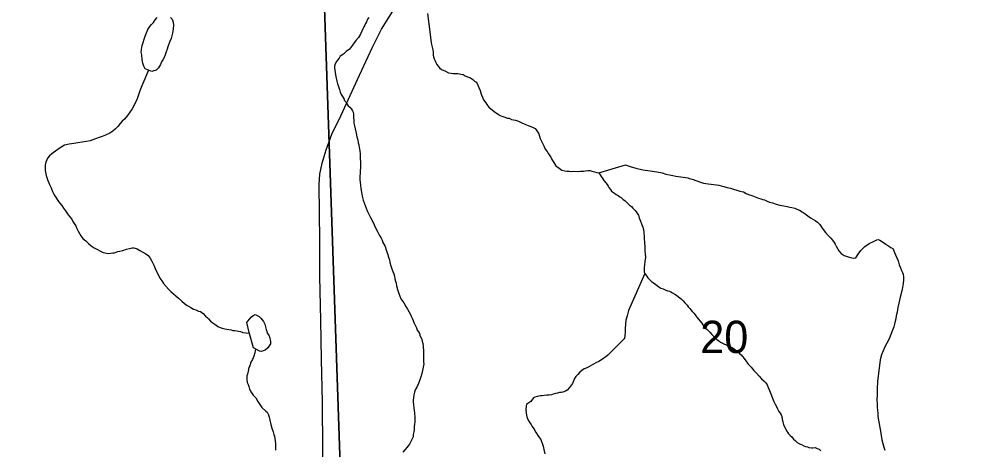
# Model space of a CAD drawing. Extents: x 2010165 to 2382125, y 1060529 to 1407316.
# Drawn here: x 2179406 to 2185920, y 1218222 to 1221171 of the extents above; entities that cross this region are included whole.
import ezdxf

# ---------------------------------------------------------------- set-up
doc = ezdxf.new("R2010")
doc.units = 0
for name, color, linetype in [('GM_X_Minor_Lake', 7, 'Continuous'), ('GM_X_Minor_River', 7, 'Continuous'), ('GM_X_Section', 7, 'Continuous'), ('GM_X_Section_Text', 7, 'Continuous'), ('GM_X_State_Route', 7, 'Continuous')]:
    doc.layers.add(name, color=color, linetype=linetype)

msp = doc.modelspace()

# ---------------------------------------------------------------- linework, layer by layer
at = {"layer": 'GM_X_Minor_Lake'}
for points in [[(2180270.6, 1221054.4), (2180278, 1221076.7), (2180287.4, 1221099), (2180300.9, 1221119.5), (2180312.6, 1221133.8), (2180326.2, 1221148.2), (2180337.7, 1221166.6), (2180351.4, 1221181)], [(2180443.6, 1221181.4), (2180454, 1221169.7), (2180460.5, 1221149.8), (2180463.1, 1221129.7), (2180461.8, 1221103.6), (2180456.6, 1221073.3), (2180447.5, 1221039), (2180436.2, 1221012.6), (2180430.6, 1220994.4), (2180425, 1220980.1), (2180421.4, 1220964), (2180413.8, 1220947.7), (2180406.4, 1220925.5), (2180398.9, 1220907.2), (2180391.2, 1220892.9), (2180381.6, 1220878.6), (2180374.1, 1220860.3), (2180360.7, 1220837.9), (2180345.1, 1220821.4), (2180323.2, 1220814.8), (2180315.2, 1220812.6)], [(2180315.2, 1220812.6), (2180270.6, 1220829.5), (2180260.1, 1220849.3), (2180253.5, 1220869.2), (2180248.8, 1220895.2), (2180246, 1220925.2), (2180243.5, 1220945.3), (2180245, 1220963.4), (2180248.3, 1220989.6), (2180270.6, 1221054.4)], [(2180965.2, 1219093.7), (2180972.9, 1219103.1), (2180984.6, 1219117.4), (2180996.3, 1219129.8), (2181010, 1219142.2), (2181023.9, 1219148.6), (2181036, 1219142.9), (2181050.3, 1219135.2), (2181062.6, 1219123.5), (2181071, 1219111.7), (2181081.3, 1219099.9), (2181089.8, 1219082.1), (2181094.3, 1219064.1), (2181098.8, 1219046.2), (2181103.2, 1219032.2), (2181105.5, 1219022.2), (2181115.9, 1219006.5), (2181124.4, 1218988.6), (2181126.7, 1218976.6), (2181129.1, 1218964.6), (2181127.5, 1218948.5), (2181119.9, 1218934.3), (2181110.2, 1218920), (2181092.6, 1218905.4), (2181078.7, 1218899.1), (2181066.7, 1218896.7), (2181052.7, 1218898.4), (2181011.9, 1218921.4), (2180983.3, 1219026.8)], [(2180983.3, 1219026.8), (2180965.2, 1219093.7)]]:
    msp.add_lwpolyline(points, dxfattribs=at)
at = {"layer": 'GM_X_Minor_River'}
for points in [[(2182205.1, 1221208.1), (2182228.9, 1221011.5), (2182231.3, 1220997.6), (2182235.9, 1220977.6), (2182240.4, 1220959.6), (2182242.8, 1220943.6), (2182243.1, 1220933.6), (2182243.3, 1220923.6), (2182245.7, 1220911.6), (2182250, 1220899.6), (2182256.4, 1220885.8), (2182260.7, 1220873.8), (2182267.1, 1220859.9), (2182277.5, 1220848.2), (2182285.8, 1220836.3), (2182300.2, 1220824.7), (2182326.5, 1220813.3), (2182346.8, 1220803.8), (2182365, 1220800.3), (2182377.1, 1220798.6), (2182397.1, 1220799.1), (2182411.2, 1220797.5), (2182423.3, 1220795.8), (2182433.3, 1220794), (2182447.5, 1220790.4), (2182461.7, 1220782.7), (2182478, 1220775.1), (2182498.2, 1220767.6), (2182514.5, 1220758), (2182526.9, 1220746.3), (2182539.1, 1220738.6), (2182564.7, 1220681), (2182571.4, 1220657.1), (2182579.9, 1220637.2), (2182586.3, 1220623.4), (2182594.7, 1220609.5), (2182603.1, 1220597.7), (2182611.4, 1220585.9), (2182623.9, 1220568.1), (2182648.5, 1220546.7), (2182669, 1220531.2), (2182687.4, 1220519.6), (2182701.7, 1220509.9), (2182713.8, 1220506.2), (2182734.1, 1220498.7), (2182752.3, 1220493.2), (2182764.3, 1220491.5), (2182780.6, 1220483.9), (2182806.8, 1220478.6), (2182827.1, 1220471.1), (2182849.4, 1220461.6), (2182871.7, 1220452.2), (2182894, 1220442.7), (2182912.2, 1220435.2), (2182928.5, 1220427.6), (2182940.7, 1220421.8), (2182949, 1220412), (2182957.3, 1220400.2), (2182965.7, 1220386.4), (2182976.6, 1220354.5), (2182987.3, 1220330.7), (2183000, 1220302.9), (2183010.6, 1220281.1), (2183023.2, 1220263.4), (2183033.6, 1220247.6), (2183042, 1220235.8), (2183048.2, 1220225.9), (2183052.6, 1220214), (2183060.9, 1220202.1), (2183069.3, 1220188.3), (2183083.9, 1220166.6), (2183106.4, 1220151.1), (2183124.8, 1220137.6), (2183145, 1220132.1), (2183159.1, 1220130.4), (2183175.2, 1220128.8), (2183191.3, 1220127.3), (2183201.2, 1220129.5), (2183235.4, 1220128.4), (2183251.4, 1220128.8), (2183273.4, 1220129.4), (2183285.4, 1220131.8), (2183301.4, 1220134.2), (2183317.4, 1220134.6), (2183329.5, 1220130.9), (2183347.7, 1220125.3), (2183363.9, 1220121.8), (2183378, 1220118.1), (2183386.4, 1220104.3), (2183392.7, 1220094.4), (2183405.2, 1220076.7), (2183411.5, 1220066.8), (2183426, 1220049.1), (2183434.3, 1220039.3), (2183440.6, 1220027.4), (2183446.9, 1220017.5), (2183457.3, 1220003.7), (2183463.6, 1219993.9)], [(2181801.2, 1221181), (2181793.5, 1221170.8), (2181786, 1221152.5), (2181780.3, 1221140.3), (2181774.5, 1221130.1), (2181768.9, 1221117.9), (2181761.2, 1221103.6), (2181753.6, 1221087.4), (2181744.2, 1221067.1), (2181730.7, 1221044.6), (2181713.2, 1221024.1), (2181690, 1220991.3), (2181668.7, 1220964.7), (2181647.1, 1220948), (2181629.5, 1220931.5), (2181617.7, 1220923.2), (2181605.8, 1220916.8), (2181598.2, 1220902.6), (2181588.5, 1220890.3), (2181580.8, 1220880), (2181571.2, 1220863.7), (2181567.5, 1220849.6), (2181565.9, 1220837.5), (2181573.2, 1220789.5), (2181577.8, 1220767.5), (2181582.4, 1220745.6), (2181586.9, 1220727.6), (2181593.4, 1220709.7), (2181600, 1220687.8), (2181606.5, 1220669.9), (2181612.9, 1220654), (2181621.3, 1220640.1), (2181629.7, 1220626.3), (2181634, 1220616.4), (2181644.3, 1220604.6), (2181648.6, 1220594.7), (2181661.1, 1220576.9), (2181671.4, 1220567.2), (2181683.8, 1220553.4), (2181690.1, 1220543.6), (2181694.4, 1220533.6), (2181696.8, 1220519.6), (2181697.3, 1220497.6), (2181699.9, 1220475.6), (2181700.4, 1220457.5), (2181704.9, 1220439.6), (2181709.5, 1220419.6), (2181714.3, 1220389.6), (2181721, 1220365.7), (2181725.6, 1220341.7), (2181730.1, 1220323.8), (2181734.5, 1220309.8), (2181737, 1220291.8), (2181739.6, 1220269.8), (2181742.2, 1220245.8), (2181742.9, 1220219.7), (2181745.8, 1220189.6), (2181744.6, 1220159.5), (2181743.5, 1220125.3), (2181741.9, 1220111.2), (2181740.2, 1220097.1), (2181740.6, 1220085.1), (2181740.9, 1220071), (2181743.4, 1220055), (2181743.9, 1220035), (2181746.6, 1220010.9), (2181751.2, 1219987), (2181756, 1219959), (2181762.8, 1219931.1), (2181790.8, 1219859.5), (2181801.4, 1219835.7), (2181814.1, 1219811.9), (2181826.8, 1219788.2), (2181839.5, 1219762.4), (2181850.2, 1219736.6), (2181862.9, 1219712.8), (2181875.6, 1219689.1), (2181886.1, 1219671.3), (2181894.5, 1219657.4), (2181898.9, 1219641.5), (2181905.2, 1219629.6), (2181911.6, 1219617.7), (2181915.9, 1219607.8), (2181918.2, 1219595.8), (2181922.5, 1219583.9), (2181926.9, 1219571.9), (2181931.2, 1219560), (2181935.5, 1219548.1), (2181939.9, 1219534.1), (2181944.2, 1219522.2), (2181946.7, 1219504.2), (2181953.3, 1219482.3), (2181959.9, 1219462.4), (2181966.4, 1219442.5), (2181972.9, 1219426.6), (2181977.3, 1219410.6)], [(2180292.5, 1220821.2), (2180247.7, 1220714.5), (2180232.6, 1220679.9), (2180212.1, 1220619.2), (2180181.8, 1220556.1), (2180148.9, 1220511.1), (2180127.5, 1220486.4), (2180111.8, 1220471.9), (2180098.2, 1220455.5), (2180082.7, 1220435), (2180067.2, 1220418.6), (2180047.5, 1220404), (2180027.8, 1220389.4), (2179998.1, 1220376.6), (2179976.3, 1220368), (2179954.4, 1220359.4), (2179930.6, 1220350.7), (2179910.7, 1220344.2), (2179892.9, 1220337.7), (2179868.9, 1220333), (2179839, 1220328.2), (2179809, 1220323.4), (2179781.1, 1220318.7), (2179749.1, 1220315.8), (2179717.2, 1220307), (2179681.7, 1220285.9), (2179656.1, 1220267.2), (2179640.4, 1220254.7), (2179630.6, 1220248.5), (2179614.9, 1220234), (2179601.3, 1220219.6), (2179595.6, 1220207.4), (2179590, 1220191.2), (2179584.5, 1220170.9), (2179585.5, 1220134.8), (2179592.4, 1220100.9), (2179603.4, 1220067), (2179614.2, 1220039.2), (2179626.8, 1220015.4), (2179635.5, 1219991.6), (2179641.9, 1219977.7), (2179650.3, 1219961.8), (2179675.5, 1219922.3), (2179685.8, 1219910.6), (2179698.3, 1219894.8), (2179710.8, 1219877.1), (2179723.3, 1219857.3), (2179737.9, 1219837.6), (2179752.4, 1219819.9), (2179766.9, 1219802.3), (2179775.4, 1219786.4), (2179783.8, 1219770.6), (2179794.3, 1219754.8), (2179802.8, 1219736.9), (2179811.3, 1219719.1), (2179819.7, 1219703.3), (2179830.2, 1219687.5), (2179842.7, 1219669.7), (2179863.2, 1219652.2), (2179881.7, 1219634.6), (2179900.2, 1219619), (2179920.6, 1219605.5), (2179943, 1219594.1), (2179963.4, 1219582.5), (2179981.7, 1219573), (2180003.8, 1219569.6), (2180020, 1219565.9), (2180033.9, 1219568.3), (2180047.9, 1219570.7), (2180059.9, 1219571), (2180071.8, 1219575.3), (2180081.8, 1219579.6), (2180095.7, 1219582), (2180115.7, 1219586.6), (2180141.5, 1219595.3), (2180163.4, 1219599.8), (2180181.4, 1219604.3), (2180191.4, 1219604.6), (2180201.5, 1219602.8), (2180215.6, 1219597.2), (2180233.9, 1219587.6), (2180254.3, 1219576.1), (2180274.7, 1219564.6), (2180291, 1219553), (2180303.5, 1219535.3), (2180316.2, 1219513.5), (2180328.9, 1219485.7), (2180341.9, 1219451.9), (2180358.7, 1219422.3), (2180371.4, 1219398.5), (2180384, 1219378.8), (2180394.5, 1219361), (2180429.6, 1219321.7), (2180446.1, 1219306.1), (2180464.5, 1219290.5), (2180481, 1219276.9), (2180497.4, 1219261.3), (2180520.1, 1219239.8), (2180538.5, 1219224.2), (2180556.9, 1219210.6), (2180575.2, 1219201.1)], [(2183378, 1220118.1), (2183561, 1220173.1), (2183591.4, 1220161.9), (2183631.8, 1220150.9), (2183680.2, 1220140.1), (2183728.6, 1220131.4), (2183774.9, 1220124.5), (2183811.2, 1220117.5), (2183837.4, 1220110.1), (2183861.7, 1220104.7), (2183883.8, 1220101.3), (2183906, 1220095.9), (2183922.1, 1220092.3), (2183940.2, 1220090.7), (2183956.3, 1220089.1), (2183972.5, 1220085.6), (2183986.5, 1220083.9), (2183996.7, 1220080.2), (2184008.8, 1220076.5), (2184024.9, 1220072.9), (2184043.2, 1220065.3), (2184067.4, 1220057.9), (2184093.8, 1220048.6), (2184126, 1220043.4), (2184148.1, 1220042), (2184164.2, 1220038.4), (2184184.3, 1220036.9), (2184200.5, 1220033.3), (2184216.6, 1220029.7), (2184234.8, 1220024.2), (2184257, 1220018.8), (2184279.2, 1220013.3), (2184343.9, 1219992.9), (2184354, 1219991.2), (2184368.1, 1219987.6), (2184386.4, 1219978), (2184402.7, 1219970.4), (2184425, 1219962.9), (2184449.3, 1219953.5), (2184471.5, 1219946.1), (2184487.7, 1219940.5), (2184499.8, 1219936.8), (2184512, 1219933.1), (2184530.2, 1219925.6), (2184546.5, 1219917.9), (2184566.7, 1219912.5), (2184592.9, 1219905.1), (2184617.2, 1219897.7), (2184645.4, 1219892.4), (2184667.6, 1219887), (2184685.8, 1219883.5), (2184699.9, 1219881.8), (2184720.1, 1219876.3), (2184734.2, 1219870.7), (2184752.5, 1219863.1), (2184770.9, 1219851.6), (2184791.3, 1219838.1), (2184809.7, 1219824.5), (2184828.1, 1219810.9), (2184844.4, 1219801.3), (2184858.7, 1219791.6), (2184875.1, 1219780), (2184891.5, 1219764.4), (2184908.3, 1219738.7), (2184931.1, 1219711.2), (2184949.7, 1219689.6), (2184966.2, 1219672), (2184978.6, 1219658.2), (2184991.1, 1219642.5), (2184997.4, 1219630.6), (2185003.8, 1219616.8), (2185012.2, 1219600.9), (2185022.7, 1219585.1), (2185037.2, 1219567.4), (2185057.7, 1219551.9), (2185092.1, 1219540.8), (2185120.3, 1219535.5), (2185138.3, 1219535.9), (2185153.6, 1219562.5), (2185173, 1219587.1), (2185200.4, 1219613.9), (2185229.9, 1219634.8), (2185259.6, 1219649.6), (2185281.4, 1219660.2), (2185291.3, 1219662.5), (2185303.5, 1219656.8), (2185321.8, 1219647.2), (2185344.3, 1219629.7), (2185364.8, 1219616.2), (2185379.1, 1219606.6), (2185393.3, 1219598.9), (2185397.7, 1219584.9), (2185404, 1219573.1), (2185410.5, 1219557.2), (2185419, 1219537.3), (2185427.6, 1219515.5), (2185436.3, 1219489.6), (2185445, 1219467.7), (2185451.5, 1219449.8)], [(2183463.6, 1219993.9), (2183484.1, 1219978.3), (2183496.3, 1219970.6), (2183510.5, 1219963), (2183520.8, 1219955.2), (2183530.9, 1219949.4), (2183543.3, 1219937.7), (2183557.6, 1219926.1), (2183576.2, 1219908.5), (2183588.5, 1219896.8), (2183600.8, 1219887.1), (2183611.1, 1219877.3), (2183627.6, 1219861.6), (2183633.9, 1219851.8), (2183648.5, 1219828.1), (2183655, 1219810.2), (2183678.8, 1219746.5), (2183683.2, 1219730.6), (2183685.8, 1219710.6), (2183686, 1219700.5), (2183688.4, 1219686.6), (2183688.9, 1219670.5), (2183689.7, 1219640.4), (2183692.4, 1219614.4), (2183693.2, 1219584.3), (2183695.8, 1219562.2), (2183696.4, 1219540.2), (2183693.1, 1219512), (2183689.8, 1219487.8), (2183688.3, 1219469.7), (2183688.5, 1219459.6), (2183688.8, 1219449.6), (2183689.1, 1219439.6), (2183693.4, 1219429.7), (2183703.8, 1219413.9), (2183714.2, 1219400.1), (2183726.6, 1219386.4), (2183739, 1219374.6), (2183751.3, 1219364.9), (2183767.6, 1219353.3), (2183788.1, 1219337.8), (2183802.3, 1219330.1), (2183818.5, 1219324.5), (2183832.8, 1219316.9), (2183848.9, 1219311.3), (2183861.1, 1219307.6), (2183871.2, 1219303.8), (2183881.4, 1219298.1), (2183897.7, 1219288.5), (2183909.9, 1219280.8), (2183924.3, 1219269.1), (2183940.7, 1219255.5), (2183955.1, 1219241.8), (2183967.5, 1219228.1), (2183982, 1219212.4), (2183990.3, 1219200.5), (2184000.6, 1219190.8), (2184006.9, 1219180.9), (2184017.2, 1219169.1), (2184027.6, 1219157.3), (2184037.9, 1219145.6), (2184046.2, 1219133.8), (2184083.6, 1219088.6), (2184098.3, 1219062.8), (2184120.8, 1219045.3), (2184137.3, 1219027.7), (2184151.8, 1219012), (2184168.3, 1218996.4), (2184184.7, 1218980.8), (2184199.1, 1218969.1), (2184211.4, 1218959.4), (2184225.6, 1218951.7), (2184237.8, 1218946), (2184252, 1218940.4), (2184264.2, 1218934.7), (2184280.4, 1218927.1), (2184290.6, 1218923.3), (2184309, 1218909.8), (2184321.2, 1218902), (2184331.5, 1218892.3), (2184341.8, 1218882.5), (2184352.1, 1218872.7), (2184362.4, 1218861), (2184372.8, 1218847.2), (2184385.3, 1218831.4), (2184399.9, 1218809.7), (2184420.5, 1218788.2), (2184439.2, 1218766.6), (2184457.7, 1218747), (2184476.3, 1218727.4), (2184492.9, 1218707.8), (2184509.3, 1218692.1), (2184521.7, 1218680.4), (2184532.1, 1218666.6), (2184538.6, 1218648.8), (2184547.1, 1218628.9), (2184555.8, 1218605), (2184568.6, 1218575.2), (2184577.3, 1218553.4), (2184585.8, 1218535.5), (2184594.2, 1218519.7)], [(2185451.5, 1219449.8), (2185457.9, 1219435.9), (2185462.2, 1219424), (2185464.7, 1219406), (2185465.2, 1219385.9), (2185461.8, 1219361.8), (2185455, 1219319.4), (2185442.4, 1219266.9), (2185433.4, 1219226.5), (2185426.2, 1219196.2), (2185421, 1219165.9), (2185415.7, 1219139.7), (2185412.2, 1219119.5), (2185408.7, 1219103.3), (2185403.2, 1219083.1), (2185397.7, 1219064.9), (2185390.2, 1219042.6), (2185379, 1219012.2), (2185365.8, 1218981.7), (2185350.5, 1218953.2), (2185337.2, 1218926.8), (2185325.9, 1218900.4), (2185314.6, 1218872), (2185305.5, 1218839.6), (2185287.4, 1218690.5), (2185284.8, 1218640.3), (2185283.9, 1218598.1), (2185282.8, 1218565.9), (2185283.5, 1218537.8), (2185284.2, 1218513.8), (2185286.8, 1218491.8), (2185289.3, 1218473.7), (2185289.9, 1218451.7), (2185292.6, 1218425.6), (2185297.2, 1218401.7), (2185302, 1218375.7), (2185306.7, 1218349.7), (2185311.5, 1218319.7), (2185316.2, 1218291.7), (2185323, 1218265.8), (2185329.7, 1218239.9), (2185336.2, 1218220)], [(2181977.3, 1219410.6), (2181979.8, 1219392.6), (2181984.3, 1219376.7), (2181988.6, 1219362.7), (2181991.1, 1219344.7), (2181997.8, 1219320.8), (2182008.6, 1219293), (2182021.6, 1219255.2), (2182042.4, 1219227.6), (2182055.1, 1219203.8), (2182067.6, 1219186.1), (2182076.1, 1219170.3), (2182084.6, 1219152.4), (2182093, 1219136.6), (2182099.4, 1219122.7), (2182105.8, 1219108.8), (2182110.2, 1219094.9), (2182116.6, 1219081), (2182123, 1219067.1), (2182129.2, 1219057.2), (2182133.7, 1219041.3), (2182142, 1219029.4), (2182148.3, 1219019.6), (2182152.6, 1219007.6), (2182165.5, 1218977.8), (2182167.8, 1218965.9), (2182172.2, 1218949.9), (2182174.7, 1218933.9), (2182175.7, 1218895.8), (2182176.5, 1218865.7), (2182177.2, 1218841.6), (2182177.7, 1218821.6), (2182178, 1218811.5), (2182174.6, 1218787.3), (2182169.2, 1218765.1), (2182161.9, 1218736.8), (2182152.7, 1218708.4), (2182141.5, 1218676), (2182130.1, 1218651.6), (2182120.6, 1218633.3), (2182115, 1218617.1), (2182111.5, 1218598.9), (2182108, 1218578.8), (2182106.5, 1218562.7), (2182104.8, 1218550.6), (2182107.3, 1218530.6), (2182109.9, 1218508.5), (2182112.4, 1218492.5), (2182114.8, 1218478.6), (2182115.1, 1218466.5), (2182117.5, 1218452.5), (2182117.7, 1218442.5), (2182118.1, 1218428.4), (2182116.5, 1218412.3), (2182114.9, 1218398.2), (2182113.3, 1218382.1), (2182111.9, 1218362), (2182110.3, 1218345.9), (2182106.8, 1218327.7), (2182105.2, 1218311.6), (2182101.5, 1218301.5), (2182080.5, 1218260.8), (2182063.1, 1218238.2), (2182035.8, 1218207.4)], [(2183693.1, 1219430.2), (2183579.9, 1219175.7), (2183570.8, 1219139.3), (2183563.6, 1219109), (2183560.4, 1219080.8), (2183559.1, 1219054.7), (2183557.8, 1219028.5), (2183556.4, 1219004.4), (2183553, 1218984.2), (2183533.5, 1218963.6), (2183510, 1218940.9), (2183482.7, 1218914.1), (2183457.3, 1218889.3), (2183439.7, 1218870.8), (2183426, 1218858.4), (2183412.2, 1218850), (2183396.5, 1218837.6), (2183376.7, 1218827), (2183356.9, 1218818.4), (2183309.5, 1218791.1), (2183291.7, 1218782.6), (2183277.8, 1218776.2), (2183262.1, 1218765.8), (2183248.4, 1218753.3), (2183234.7, 1218738.9), (2183221.1, 1218724.5), (2183211.4, 1218710.2), (2183198.3, 1218677.7), (2183177, 1218649.1), (2183161.4, 1218630.6), (2183149.6, 1218624.2), (2183131.7, 1218617.8), (2183119.7, 1218615.4), (2183107.7, 1218615.1), (2183093.8, 1218610.7), (2183079.8, 1218608.3), (2183065.9, 1218604), (2183054, 1218599.6), (2183038, 1218597.2), (2183022, 1218596.8), (2183004, 1218594.3), (2182990, 1218591.9), (2182978, 1218591.6), (2182966, 1218589.3), (2182956.1, 1218587), (2182940.1, 1218582.6), (2182930.2, 1218578.3), (2182910.8, 1218553.7), (2182891.2, 1218539.1), (2182881.3, 1218532.8), (2182879.6, 1218522.8), (2182878.2, 1218498.6), (2182878.9, 1218474.6), (2182883.6, 1218448.6), (2182894.3, 1218424.8), (2182904.8, 1218407), (2182913.1, 1218395.1), (2182921.5, 1218383.3), (2182931.9, 1218367.5), (2182940.3, 1218355.7), (2182948.7, 1218339.8), (2182959.3, 1218320.1), (2182971.7, 1218304.3), (2182980.1, 1218292.5), (2182995.3, 1218246.7), (2183001.9, 1218224.8), (2183006.7, 1218194.8)], [(2180575.2, 1219201.1), (2180589.5, 1219191.4), (2180601.7, 1219185.7), (2180615.9, 1219180), (2180634.2, 1219172.5), (2180648.3, 1219168.8), (2180666.7, 1219155.3), (2180683.2, 1219137.6), (2180693.5, 1219127.9), (2180703.8, 1219118.1), (2180716.3, 1219102.4), (2180734.7, 1219088.8), (2180753, 1219077.2), (2180767.3, 1219067.6), (2180783.6, 1219060), (2180797.8, 1219054.3), (2180815.9, 1219050.8), (2180830, 1219049.1), (2180844.1, 1219045.5), (2180858.2, 1219043.9), (2180870.4, 1219040.2), (2180882.4, 1219038.5), (2180898.5, 1219036.9), (2180908.6, 1219035.1), (2180922.7, 1219031.5), (2180938.9, 1219025.9), (2180985, 1219020.7)], [(2181025.4, 1218913.8), (2181020.9, 1218885.5), (2181013.5, 1218863.2), (2181004.1, 1218840.9), (2180994.5, 1218822.6), (2180987.2, 1218798.3), (2180979.5, 1218786), (2180976.1, 1218761.8), (2180970.6, 1218741.6), (2180967, 1218729.5), (2180965.3, 1218717.4), (2180965.7, 1218703.3), (2180968.2, 1218683.3), (2180974.6, 1218669.4), (2180979, 1218655.5), (2180983.5, 1218637.5), (2180996.1, 1218617.8), (2181010.7, 1218596.1), (2181027.2, 1218578.4), (2181041.9, 1218552.7), (2181069.1, 1218511.3), (2181095.8, 1218487.9), (2181106, 1218480.1), (2181114.5, 1218462.3), (2181119, 1218446.3), (2181123.5, 1218426.4), (2181130.4, 1218396.4), (2181137.1, 1218370.5), (2181145.7, 1218346.6), (2181152.2, 1218328.7), (2181156.6, 1218316.8), (2181161.4, 1218284.8), (2181162, 1218264.7), (2181162.6, 1218242.7), (2181163.2, 1218220.6)], [(2184594.2, 1218519.7), (2184602.7, 1218503.9), (2184611.2, 1218486), (2184619.5, 1218474.2), (2184625.8, 1218462.3), (2184632.2, 1218450.4), (2184634.7, 1218430.4), (2184639.2, 1218414.5), (2184643.6, 1218396.5), (2184662.9, 1218352.8), (2184671.2, 1218343), (2184677.4, 1218333.1), (2184687.8, 1218321.4), (2184700.1, 1218311.7), (2184712.5, 1218295.9), (2184722.8, 1218286.1), (2184737.2, 1218272.5), (2184751.5, 1218264.8), (2184765.7, 1218259.2), (2184782, 1218249.6), (2184794.1, 1218245.9), (2184806.2, 1218244.2), (2184816.4, 1218238.4), (2184834.5, 1218236.9), (2184844.5, 1218237.1), (2184860.4, 1218239.6), (2184872.7, 1218231.9), (2184886.9, 1218226.2), (2184899.2, 1218216.5)]]:
    msp.add_lwpolyline(points, dxfattribs=at)
at = {"layer": 'GM_X_Section'}
for points in [[(2185647.9, 1221682.3), (2186866.2, 1221693.3), (2186961.3, 1216421.1), (2181662, 1216455.1), (2181485, 1221648.7), (2182193.8, 1221655.1)], [(2178737.9, 1221615.8), (2181485, 1221648.7), (2181662, 1216455.1), (2176133.3, 1216538.6), (2176081.6, 1221585.6)]]:
    msp.add_lwpolyline(points, close=True, dxfattribs=at)
at = {"layer": 'GM_X_State_Route'}
msp.add_lwpolyline([(2181493.7, 1217846.1), (2181487.3, 1218223), (2181485, 1218549.8), (2181478.7, 1218840.5), (2181472.5, 1219109.1), (2181466.2, 1219409.9), (2181466, 1219662.5), (2181463.8, 1219838.9), (2181461.6, 1220041.4), (2181465.6, 1220109.6), (2181483.5, 1220183.8), (2181509.5, 1220276), (2181549.4, 1220382.3), (2181611.4, 1220508.6), (2181737.3, 1220787.4), (2181827.3, 1220977.9), (2181889.3, 1221102.2), (2182029.1, 1221325)], dxfattribs=at)

# ---------------------------------------------------------------- texts
at = {"layer": 'GM_X_Section_Text'}
msp.add_text('20', height=221, rotation=0.00001, dxfattribs=at).set_placement((2184072.8, 1218885.1))

doc.saveas('drawing.dxf')
